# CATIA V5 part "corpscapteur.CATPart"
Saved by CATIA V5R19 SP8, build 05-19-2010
Part number: corpscapteur
Revision: ANY
Definition: UNKNOWN
Nomenclature: corpscapteur
Source: Unknown
Bounding box of the stored display mesh (mm): x -6.375 to 6.375, y -2.885 to 2.885, z 0 to 5.95
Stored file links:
  D:\Documents\1_Travail\1 - ac-limoges.fr\ac-limoges.fr\Emmanuel Maynard - STI2D_Turgot\2 -2I2D\2_SEQUENCE_Serrure_Biométrique\5-Spé_ITEC\Serrure_Bio_Eleve\corpscapteur.CATPart
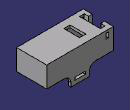
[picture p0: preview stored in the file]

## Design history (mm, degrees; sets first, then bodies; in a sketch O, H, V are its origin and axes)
Body1 "Enlèv. mat.-Extru.4" (main body)
  Solid1: solid without history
